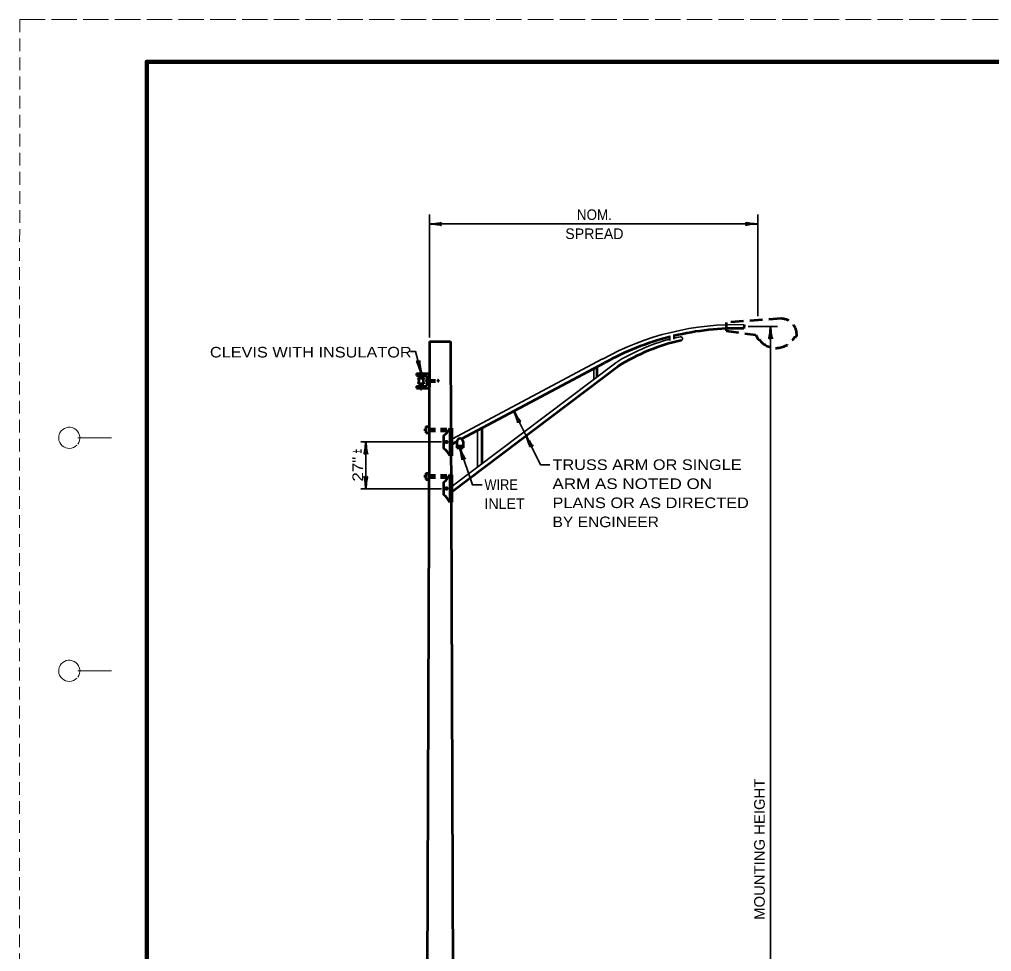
# Model space of a CAD drawing. Extents: x -1 to 679, y 0 to 440.
# Drawn here: x -1.2 to 228.3, y 220.2 to 440.2 of the extents above; entities that cross this region are included whole.
import ezdxf
from ezdxf.enums import TextEntityAlignment as Align

# ---------------------------------------------------------------- set-up
doc = ezdxf.new("R2010")
doc.units = 0
for name, pattern in [('LONG_DASHED', [7.5, 6, -1.5]), ('MEDIUM_DASHED', [4.5, 3, -1.5]), ('SHORT_DASHED', [2.7, 1.5, -1.2])]:
    doc.linetypes.add(name, pattern=pattern)
doc.layers.add('1', color=7, linetype='Continuous', lineweight=53)
doc.layers.add('61', color=7, linetype='Continuous', lineweight=35)

msp = doc.modelspace()

# ---------------------------------------------------------------- linework, layer by layer
at = {"layer": '1', "linetype": 'MEDIUM_DASHED', "lineweight": 13}
msp.add_line((-1.129, 440.242), (-1.189, 0.202), dxfattribs=at)
at = {"layer": '1', "lineweight": 35}
for p, q in [((95.605, 365.184), (95.605, 394.184)), ((173.155, 370.227), (173.155, 394.184)), ((95.605, 391.973), (173.155, 391.973)), ((170.887, 367.754), (177.77, 367.754)), ((176.14, 105.337), (176.14, 367.754)), ((100.889, 341.154), (136.489, 360.094)), ((100.95, 330.074), (139.589, 359.194)), ((134.41, 357.834), (134.41, 355.294)), ((106.95, 343.374), (106.95, 334.774)), ((98.448, 340.508), (79.38, 340.508)), ((80.596, 329.475), (80.596, 340.508)), ((121.858, 335.102), (124.036, 335.102)), ((98.448, 329.475), (79.38, 329.475))]:
    msp.add_line(p, q, dxfattribs=at)
at = {"layer": '1'}
for p, q in [((169.897, 368.169), (169.877, 367.292)), ((95.605, 364.184), (94.605, 62.184)), ((95.605, 364.184), (100.605, 364.184)), ((100.605, 364.184), (100.673, 343.748)), ((100.95, 328.814), (140.189, 358.394)), ((103.165, 341.224), (136.969, 359.194)), ((135.169, 358.234), (135.169, 355.854)), ((92.525, 356.695), (95.525, 356.695)), ((92.525, 356.695), (92.525, 356.195)), ((92.525, 356.195), (95.025, 356.195)), ((93.525, 356.195), (93.525, 355.695)), ((93.775, 356.195), (93.775, 355.695)), ((95.025, 356.195), (95.025, 353.695)), ((95.525, 356.695), (95.525, 353.195)), ((92.525, 353.695), (95.025, 353.695)), ((92.525, 353.695), (92.525, 353.195)), ((93.025, 355.695), (94.275, 355.695)), ((93.025, 355.695), (93.025, 355.57)), ((93.025, 355.57), (94.275, 355.57)), ((93.025, 354.32), (94.275, 354.32)), ((93.025, 354.32), (93.025, 354.195)), ((93.025, 354.195), (94.275, 354.195)), ((93.525, 354.195), (93.525, 353.695)), ((93.775, 354.195), (93.775, 353.695)), ((94.275, 355.695), (94.275, 355.57)), ((94.275, 354.32), (94.275, 354.195)), ((92.525, 353.195), (95.525, 353.195)), ((93.525, 353.195), (93.525, 352.945)), ((93.525, 352.945), (93.775, 352.945)), ((93.775, 353.195), (93.775, 352.945)), ((94.545, 343.637), (94.795, 343.637)), ((94.545, 343.637), (94.545, 343.137)), ((94.545, 343.137), (94.795, 343.137)), ((94.795, 344.137), (94.795, 342.637)), ((94.795, 344.137), (95.545, 344.137)), ((94.795, 342.637), (95.545, 342.637)), ((95.545, 344.137), (95.545, 342.637)), ((98.905, 341.998), (98.905, 338.998)), ((100.405, 343.748), (100.405, 337.248)), ((100.905, 343.748), (100.405, 343.748)), ((100.905, 343.748), (100.905, 337.248)), ((107.95, 343.774), (107.95, 335.354)), ((100.905, 340.023), (102.053, 340.632)), ((102.053, 340.617), (102.053, 339.117)), ((103.553, 340.617), (103.553, 339.117)), ((102.053, 339.617), (103.553, 339.617)), ((102.053, 339.117), (103.553, 339.117)), ((100.905, 337.248), (100.405, 337.248)), ((100.694, 337.248), (100.709, 332.766)), ((94.758, 333.145), (94.758, 331.645)), ((94.758, 333.145), (95.508, 333.145)), ((95.508, 333.145), (95.508, 331.645)), ((94.508, 332.645), (94.758, 332.645)), ((94.508, 332.645), (94.508, 332.145)), ((94.508, 332.145), (94.758, 332.145)), ((94.758, 331.645), (95.508, 331.645)), ((98.905, 331.016), (98.905, 328.016)), ((100.405, 332.766), (100.405, 326.266)), ((100.905, 332.766), (100.405, 332.766)), ((100.905, 332.766), (100.905, 326.266)), ((100.905, 326.266), (100.405, 326.266)), ((100.73, 326.266), (101.605, 62.184))]:
    msp.add_line(p, q, dxfattribs=at)
at = {"layer": '1', "lineweight": 40}
for p, q in [((152.309, 365.534), (152.309, 364.494)), ((153.309, 365.794), (153.309, 364.754))]:
    msp.add_line(p, q, dxfattribs=at)
at = {"layer": '1', "linetype": 'MEDIUM_DASHED'}
for p, q in [((181.788, 365.264), (182.293, 365.299)), ((173.233, 364.659), (173.487, 364.677))]:
    msp.add_line(p, q, dxfattribs=at)
at = {"layer": '1', "linetype": 'SHORT_DASHED'}
for p, q in [((95.525, 355.07), (97.525, 355.07)), ((95.525, 354.82), (97.525, 354.82)), ((95.545, 343.637), (100.358, 343.637)), ((95.545, 343.137), (100.087, 343.137)), ((95.508, 332.645), (100.354, 332.645)), ((95.508, 332.145), (100.08, 332.145))]:
    msp.add_line(p, q, dxfattribs=at)
at = {"layer": '1', "linetype": 'MEDIUM_DASHED'}
msp.add_lwpolyline([(178.733, 369.619), (165.653, 368.699), (165.653, 366.759), (172.653, 365.779), (173.233, 364.659)], dxfattribs=at)
at = {"layer": '1', "lineweight": 35}
for points in [[(93.629, 356.854), (92.346, 361.831), (91.146, 361.831)], [(115.556, 347.774), (118.431, 341.992), (121.858, 335.102)], [(102.758, 339.117), (105.795, 330.385), (108.083, 330.385)]]:
    msp.add_lwpolyline(points, dxfattribs=at)
at = {"layer": '1'}
for centre in [(99.653, 340.499), (99.653, 329.517)]:
    msp.add_circle(centre, 0.205, dxfattribs=at)
at = {"layer": '1', "linetype": 'MEDIUM_DASHED'}
for centre, radius, start, end in [((178.61, 365.892), 3.725, 350.72659, 88.16029), ((177.45, 367.62), 4.936, 216.5956, 331.48566)]:
    msp.add_arc(centre, radius, start, end, dxfattribs=at)
at = {"layer": '1', "lineweight": 35}
for centre, radius, start, end in [((167.891, 303.399), 64.801, 88.22597, 118.97566), ((164.249, 320.116), 46.207, 101.77153, 103.69374), ((154.882, 364.897), 0.459, 287.04383, 97.53852), ((164.249, 320.116), 46.207, 104.98386, 122.26161)]:
    msp.add_arc(centre, radius, start, end, dxfattribs=at)
at = {"layer": '1'}
for centre, radius, start, end in [((168.364, 302.509), 64.801, 88.66269, 103.43313), ((168.364, 302.509), 64.801, 104.35124, 118.97566), ((164.856, 319.311), 46.207, 102.29396, 122.26161), ((93.649, 356.579), 0.276, 25.01454, 154.98546), ((91.915, 354.945), 1.274, 330.61497, 29.38503), ((95.384, 354.945), 1.274, 150.61497, 209.38503), ((95.089, 354.945), 0.258, 104.46748, 255.53251), ((97.045, 345.11), 3.626, 300.86604, 337.93136), ((102.803, 340.566), 0.752, 3.92026, 176.07974), ((97.045, 335.886), 3.626, 22.06864, 59.13396), ((97.045, 334.128), 3.626, 300.86604, 337.93136), ((97.045, 324.904), 3.626, 22.06864, 59.13396)]:
    msp.add_arc(centre, radius, start, end, dxfattribs=at)
at = {"layer": '1', "lineweight": 40}
for centre, major_axis, ratio, start_param, end_param in [((96.725, 391.761), (-1.756, 0.176), 0.07063, 3.1407148, 5.41811), ((96.696, 392.249), (-1.786, -0.156), 0.122415, 0.8963533, 3.1415927), ((172.064, 391.696), (1.786, 0.156), 0.122415, 0.8963533, 3.1415927), ((172.034, 392.184), (1.756, -0.176), 0.07063, 3.1407148, 5.41811), ((175.929, 366.634), (0.176, 1.756), 0.07063, 3.1407148, 5.41811), ((175.929, 366.634), (0.176, 1.756), 0.07063, 3.1407148, 5.41811), ((176.417, 366.663), (-0.156, 1.786), 0.122415, 0.8963533, 3.1415927), ((176.417, 366.663), (-0.156, 1.786), 0.122415, 0.8963533, 3.1415927), ((93.089, 357.842), (0.597, -1.69), 0.122415, 0.8963533, 3.1415927), ((93.554, 357.992), (-0.268, 1.745), 0.07063, 6.2823074, 8.5597026), ((115.865, 346.677), (-0.625, 1.651), 0.07063, 3.1407148, 5.41811), ((115.865, 346.677), (-0.625, 1.651), 0.07063, 3.1407148, 5.41811), ((116.289, 346.92), (-0.935, 1.529), 0.122415, 0.8963533, 3.1415927), ((116.289, 346.92), (-0.935, 1.529), 0.122415, 0.8963533, 3.1415927), ((118.741, 340.895), (0.625, -1.651), 0.07063, 6.2823074, 8.5597026), ((119.165, 341.138), (-0.935, 1.529), 0.122415, 0.8963533, 3.1415927), ((80.384, 339.387), (0.176, 1.756), 0.07063, 3.1407148, 5.41811), ((80.872, 339.417), (-0.156, 1.786), 0.122415, 0.8963533, 3.1415927), ((102.927, 337.989), (0.411, -1.717), 0.07063, 6.2823074, 8.5597026), ((103.378, 338.177), (-0.734, 1.635), 0.122415, 0.8963533, 3.1415927), ((80.319, 330.566), (0.156, -1.786), 0.122415, 0.8963533, 3.1415927), ((80.807, 330.595), (-0.176, -1.756), 0.07063, 3.1407148, 5.41811)]:
    msp.add_ellipse(centre, major_axis=major_axis, ratio=ratio, start_param=start_param, end_param=end_param, dxfattribs=at)
at = {"layer": '1', "linetype": 'SHORT_DASHED'}
msp.add_ellipse((97.525, 354.945), major_axis=(0.338, 0), ratio=0.370014, start_param=4.712389, end_param=7.8539816, dxfattribs=at)
at = {"layer": '61', "linetype": 'LONG_DASHED', "lineweight": 13}
msp.add_line((-1.129, 440.242), (678.891, 440.242), dxfattribs=at)
at = {"layer": '61', "lineweight": 13}
for p, q in [((12.591, 341.482), (20.571, 341.502)), ((12.571, 286.482), (20.571, 286.482))]:
    msp.add_line(p, q, dxfattribs=at)
at = {"layer": '61', "lineweight": 158}
msp.add_lwpolyline([(667.911, 430.242), (28.871, 430.242), (28.871, 10.222)], dxfattribs=at)
at = {"layer": '61', "lineweight": 13}
for centre, end in [((10.569, 341.483), 316.23216), ((10.569, 286.483), 315.37577)]:
    msp.add_arc(centre, 2.5, 323.13009, end, dxfattribs=at)

# ---------------------------------------------------------------- texts
at = {"layer": '1', "width": 0.95}
msp.add_text('NOM.', height=2.5, dxfattribs=at).set_placement((134.564, 392.91), align=Align.CENTER)
at = {"layer": '1'}
msp.add_text('SPREAD', height=2.5, dxfattribs=at).set_placement((134.564, 388.41), align=Align.CENTER)
for s, width, p in [('CLEVIS WITH INSULATOR', 1.15, (43.782, 360.449)), ('TRUSS ARM OR SINGLE', 1.15, (124.669, 333.899)), ('WIRE', 0.9, (108.615, 329.186)), ('ARM AS NOTED ON', 1.2, (124.669, 329.399)), ('PLANS OR AS DIRECTED', 1.15, (124.669, 324.899)), ('BY ENGINEER', 1.1, (124.669, 320.399))]:
    msp.add_text(s, height=2.5, dxfattribs=dict(at, width=width)).set_placement(p)
for s, width, p in [('+', 0.55, (79.554, 337.778)), ('27"', 1.2, (79.938, 331.136)), ('MOUNTING HEIGHT', 1.05, (174.787, 227.697))]:
    msp.add_text(s, height=2.5, rotation=90, dxfattribs=dict(at, width=width)).set_placement(p)
msp.add_text('-', height=2.5, rotation=90, dxfattribs=at).set_placement((80.435, 337.778))
msp.add_text('INLET', height=2.5, dxfattribs=at).set_placement((108.615, 324.686))

doc.saveas('drawing.dxf')
